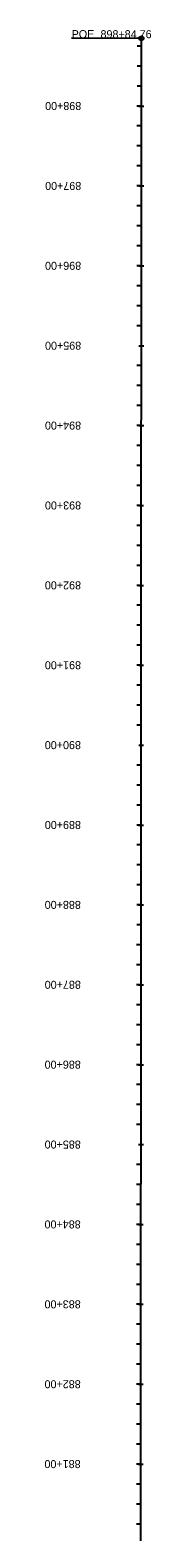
# Model space of a CAD drawing. Extents: x 18543252 to 18543633, y 7433057 to 7440612.
# Drawn here: x 18543267 to 18543400, y 7438732 to 7440612 of the extents above; entities that cross this region are included whole.
import ezdxf

# ---------------------------------------------------------------- set-up
doc = ezdxf.new("R2010")
doc.units = 0
for name, color, linetype in [('PS_BOLT', 7, 'Continuous'), ('PS_DIM', 7, 'Continuous'), ('PS_MID', 7, 'Continuous'), ('PS_SHAPE', 7, 'Continuous')]:
    doc.layers.add(name, color=color, linetype=linetype)

msp = doc.modelspace()

# ---------------------------------------------------------------- linework, layer by layer
at = {"layer": 'PS_BOLT'}
for p, q in [((18543387.6, 7440516.8), (18543382.1, 7440516.8)), ((18543387.6, 7440416.8), (18543382.1, 7440416.8)), ((18543387.5, 7440316.8), (18543382, 7440316.8)), ((18543384.4, 7440216.8), (18543390.5, 7440216.8)), ((18543387.4, 7440116.8), (18543382, 7440116.8)), ((18543387.4, 7440016.8), (18543381.9, 7440016.8)), ((18543387.3, 7439916.8), (18543381.9, 7439916.8)), ((18543387.3, 7439816.8), (18543381.8, 7439816.8)), ((18543384.2, 7439716.8), (18543390.3, 7439716.8)), ((18543387.2, 7439616.8), (18543381.7, 7439616.8)), ((18543387.1, 7439516.8), (18543381.7, 7439516.8)), ((18543387.1, 7439416.8), (18543381.6, 7439416.8)), ((18543387, 7439316.8), (18543381.6, 7439316.8)), ((18543383.9, 7439216.8), (18543390.1, 7439216.8)), ((18543386.9, 7439116.8), (18543381.5, 7439116.8)), ((18543386.9, 7439016.8), (18543381.4, 7439016.8)), ((18543386.8, 7438916.8), (18543381.4, 7438916.8)), ((18543386.8, 7438816.8), (18543381.3, 7438816.8))]:
    msp.add_line(p, q, dxfattribs=at)
at = {"layer": 'PS_DIM'}
msp.add_line((18543387.6, 7440601.5), (18543300.6, 7440601.6), dxfattribs=at)
msp.add_circle((18543387.6, 7440601.5), 2.67, dxfattribs=at)
at = {"layer": 'PS_MID'}
for p, q in [((18543387.6, 7440591.8), (18543382.2, 7440591.8)), ((18543387.6, 7440566.8), (18543382.2, 7440566.8)), ((18543387.6, 7440541.8), (18543382.2, 7440541.8)), ((18543384.5, 7440516.8), (18543390.7, 7440516.8)), ((18543387.6, 7440491.8), (18543382.1, 7440491.8)), ((18543387.6, 7440466.8), (18543382.1, 7440466.8)), ((18543387.6, 7440441.8), (18543382.1, 7440441.8)), ((18543384.5, 7440416.8), (18543390.6, 7440416.8)), ((18543387.5, 7440391.8), (18543382.1, 7440391.8)), ((18543387.5, 7440366.8), (18543382.1, 7440366.8)), ((18543387.5, 7440341.8), (18543382.1, 7440341.8)), ((18543384.4, 7440316.8), (18543390.6, 7440316.8)), ((18543387.5, 7440291.8), (18543382, 7440291.8)), ((18543387.5, 7440266.8), (18543382, 7440266.8)), ((18543387.5, 7440241.8), (18543382, 7440241.8)), ((18543384.4, 7440216.8), (18543390.5, 7440216.8)), ((18543387.4, 7440191.8), (18543382, 7440191.8)), ((18543387.4, 7440166.8), (18543382, 7440166.8)), ((18543387.4, 7440141.8), (18543382, 7440141.8)), ((18543384.4, 7440116.8), (18543390.5, 7440116.8)), ((18543387.4, 7440091.8), (18543381.9, 7440091.8)), ((18543387.4, 7440066.8), (18543381.9, 7440066.8)), ((18543387.4, 7440041.8), (18543381.9, 7440041.8)), ((18543384.3, 7440016.8), (18543390.4, 7440016.8)), ((18543387.4, 7439991.8), (18543381.9, 7439991.8)), ((18543387.3, 7439966.8), (18543381.9, 7439966.8)), ((18543387.3, 7439941.8), (18543381.9, 7439941.8)), ((18543384.3, 7439916.8), (18543390.4, 7439916.8)), ((18543387.3, 7439891.8), (18543381.8, 7439891.8)), ((18543387.3, 7439866.8), (18543381.8, 7439866.8)), ((18543387.3, 7439841.8), (18543381.8, 7439841.8)), ((18543384.2, 7439816.8), (18543390.3, 7439816.8)), ((18543387.3, 7439791.8), (18543381.8, 7439791.8)), ((18543387.2, 7439766.8), (18543381.8, 7439766.8)), ((18543387.2, 7439741.8), (18543381.8, 7439741.8)), ((18543384.2, 7439716.8), (18543390.3, 7439716.8)), ((18543387.2, 7439691.8), (18543381.8, 7439691.8)), ((18543387.2, 7439666.8), (18543381.7, 7439666.8)), ((18543387.2, 7439641.8), (18543381.7, 7439641.8)), ((18543384.1, 7439616.8), (18543390.2, 7439616.8)), ((18543387.2, 7439591.8), (18543381.7, 7439591.8)), ((18543387.2, 7439566.8), (18543381.7, 7439566.8)), ((18543387.1, 7439541.8), (18543381.7, 7439541.8)), ((18543384.1, 7439516.8), (18543390.2, 7439516.8)), ((18543387.1, 7439491.8), (18543381.7, 7439491.8)), ((18543387.1, 7439466.8), (18543381.6, 7439466.8)), ((18543387.1, 7439441.8), (18543381.6, 7439441.8)), ((18543384, 7439416.8), (18543390.1, 7439416.8)), ((18543387.1, 7439391.8), (18543381.6, 7439391.8)), ((18543387.1, 7439366.8), (18543381.6, 7439366.8)), ((18543387, 7439341.8), (18543381.6, 7439341.8)), ((18543384, 7439316.8), (18543390.1, 7439316.8)), ((18543387, 7439291.8), (18543381.6, 7439291.8)), ((18543387, 7439266.8), (18543381.6, 7439266.8)), ((18543387, 7439241.8), (18543381.5, 7439241.8)), ((18543383.9, 7439216.8), (18543390.1, 7439216.8)), ((18543387, 7439191.8), (18543381.5, 7439191.8)), ((18543387, 7439166.8), (18543381.5, 7439166.8)), ((18543387, 7439141.8), (18543381.5, 7439141.8)), ((18543383.9, 7439116.8), (18543390, 7439116.8)), ((18543386.9, 7439091.8), (18543381.5, 7439091.8)), ((18543386.9, 7439066.8), (18543381.5, 7439066.8)), ((18543386.9, 7439041.8), (18543381.4, 7439041.8)), ((18543383.8, 7439016.8), (18543390, 7439016.8)), ((18543386.9, 7438991.8), (18543381.4, 7438991.8)), ((18543386.9, 7438966.8), (18543381.4, 7438966.8)), ((18543386.9, 7438941.8), (18543381.4, 7438941.8)), ((18543383.8, 7438916.8), (18543389.9, 7438916.8)), ((18543386.8, 7438891.8), (18543381.4, 7438891.8)), ((18543386.8, 7438866.8), (18543381.4, 7438866.8)), ((18543386.8, 7438841.8), (18543381.4, 7438841.8)), ((18543383.7, 7438816.8), (18543389.9, 7438816.8)), ((18543386.8, 7438791.8), (18543381.3, 7438791.8)), ((18543386.8, 7438766.8), (18543381.3, 7438766.8)), ((18543386.8, 7438741.8), (18543381.3, 7438741.8))]:
    msp.add_line(p, q, dxfattribs=at)
at = {"layer": 'PS_SHAPE'}
msp.add_line((18543386, 7437196.1), (18543387.6, 7440601.5), dxfattribs=at)

# ---------------------------------------------------------------- texts
at = {"layer": 'PS_BOLT'}
for s, p in [('895+00', (18543312.5, 7440221.8)), ('890+00', (18543312.2, 7439721.8)), ('885+00', (18543312, 7439221.8))]:
    msp.add_text(s, height=10.02, rotation=179.973, dxfattribs=at).set_placement(p)
at = {"layer": 'PS_DIM'}
for s, p in [('POE ', (18543300.6, 7440601.8)), ('898+84.76', (18543336.6, 7440601.7))]:
    msp.add_text(s, height=10.02, rotation=359.973, dxfattribs=at).set_placement(p)
at = {"layer": 'PS_MID'}
for s, p in [('898+00', (18543312.6, 7440521.8)), ('897+00', (18543312.6, 7440421.8)), ('896+00', (18543312.5, 7440321.8)), ('895+00', (18543312.5, 7440221.8)), ('894+00', (18543312.4, 7440121.8)), ('893+00', (18543312.4, 7440021.8)), ('892+00', (18543312.3, 7439921.8)), ('891+00', (18543312.3, 7439821.8)), ('890+00', (18543312.2, 7439721.8)), ('889+00', (18543312.2, 7439621.8)), ('888+00', (18543312.1, 7439521.8)), ('887+00', (18543312.1, 7439421.8)), ('886+00', (18543312, 7439321.8)), ('885+00', (18543312, 7439221.8)), ('884+00', (18543311.9, 7439121.8)), ('883+00', (18543311.9, 7439021.8)), ('882+00', (18543311.9, 7438921.8)), ('881+00', (18543311.8, 7438821.8))]:
    msp.add_text(s, height=10.02, rotation=179.973, dxfattribs=at).set_placement(p)

doc.saveas('drawing.dxf')
